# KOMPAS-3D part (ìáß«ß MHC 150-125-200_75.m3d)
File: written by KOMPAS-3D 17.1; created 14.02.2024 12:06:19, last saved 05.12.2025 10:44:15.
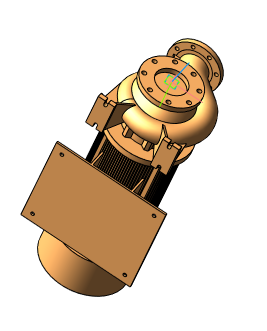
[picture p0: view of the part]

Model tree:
1. Операция без истории:3

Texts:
  ООО АДЛ Групп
